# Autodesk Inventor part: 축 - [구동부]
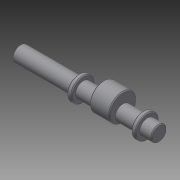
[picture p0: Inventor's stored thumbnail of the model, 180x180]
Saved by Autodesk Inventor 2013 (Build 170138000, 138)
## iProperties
Company: 한국ATC센터
Created: 2014-08
Part Number: 축 - [구동부]
Document SubType Name: Modeling
Designer: KYOUNG IL JANG
Density: 1 g/cm^3
Material: 일반
Mass: 47.7676 g
Surface Area: 117.379 cm^2
Volume: 47.7676 cm^3
Author: KYOUNG IL JANG
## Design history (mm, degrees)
sketch "스케치1"
  geometry: L1 (-76.5, 0)-(76.5, 0); L2 (-76.5, 0)-(-76.5, 8.5); L3 (-76.5, 8.5)-(-12.5, 8.5); L4 (-12.5, 8.5)-(-12.5, 13); L5 (-12.5, 13)-(-7.5, 13); L6 (-7.5, 13)-(-7.5, 8.5); L7 (-7.5, 8.5)-(58.5, 8.5); L8 (58.5, 8.5)-(58.5, 13); L9 (58.5, 13)-(63.5, 13); L10 (63.5, 13)-(63.5, 8.5); L11 (63.5, 8.5)-(76.5, 8.5); L12 (76.5, 8.5)-(76.5, 0); 2 further points
  constraints: 24 end point, 5 parallel, 1 coincident, 1 horizontal, 1 midpoint, 1 perpendicular
  dimensions: "d0" = 153 distance of L1.start L1.end (derived); "d2" = 17 diameter of L3 L1; "d3" = 26 diameter of L5 L1; "d4" = 17 diameter of L7 L1; "d5" = 26 diameter of L9 L1; "d6" = 17 diameter of L11 L1; "d7" = 5 distance of L8.end L9.end; "d8" = 5 distance of L4.end L5.end; "d10" = 64 distance of L2.end L3.end; "d11" = 13 distance of L10.end L11.end; "d35" = 66 distance between parallel lines of L8 L6
revolve "회전1" sketch "스케치1" stored, may be unused: angle "d12" = 90 deg
node "작업 평면1"
node "작업 평면2"
node "작업 평면4"
sketch "스케치6"
  geometry: C1 r 15 at (-5, -6); 1 further point
  constraints: 1 centre point, 1 horizontal alignment
  dimensions: "d31" = 30 diameter of C1; "d32" = 5 distance of C1.centre point (0, -6)
extrude "돌출4" join sketch "스케치6" stored distance "d33" = 22; taper "d34" = 0 deg
node "작업 평면3"
sketch "스케치5"
  geometry: L1 (32, 8.5)-(32, -8.5) reference; L2 (32, -2.5)-(14.5, -2.5); L3 (14.5, 2.5)-(32, 2.5); A1 r 2.5 centre (14.5, 0) between (14.5, 2.5) and (14.5, -2.5); 2 further points
  constraints: 4 end point, 2 point on circle, 2 point on line, 2 tangent, 1 centre point, 1 midpoint, 1 parallel, 1 perpendicular
  dimensions: "d23" = 5 distance between parallel lines of L3 L2; "d36" = 20 dimension on A1 L1
extrude "돌출3" cut sketch "스케치5" distance "d25" = 3; taper "d26" = 0 deg
chamfer "모따기1" distance "d27" = 1; stored, may be unused: second distance "d28" = 2, angle "d29" = 45 deg
node "솔리드1"
other parameters: "d13" = 9.5, "d18" = 9.5
